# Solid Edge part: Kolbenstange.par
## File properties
Username: bmolnar
Dokumentum tartalom típus: 0
Author: bmolnar
Last saved by: bmolnar
Revision: 79
Sűrűség: 0,000 kg/m^3
Pontosság: 0,990
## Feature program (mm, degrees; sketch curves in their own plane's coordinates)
base feature "unnamed BaseFeature 1"
sketch for "unnamed Protrusion 1" plane through (42.5, 0, 0) normal (1, 0, 0) x-axis (0, 0, -1)
  circle centre (0, 0) radius 31.5
extrude "unnamed Protrusion 1" add finite 17.85 along +normal
sketch for "Kihúzás_4" #1 plane through (42.5, 0, 0) normal (1, 0, 0) x-axis (0, 0, -1)
  circle centre (0, 0) radius 8
sketch for "Kihúzás_4" #2 plane through (42.5, 0, 0) normal (1, 0, 0) x-axis (0, 0, -1)
  circle centre (0, 0) radius 31.5
extrude "Kihúzás_4" add finite 10.85 along -normal
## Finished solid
Body 1: solid body, 14 faces, 20 edges, 8 vertices.
  Faces by surface: plane 8, cylinder 4, cone 1, torus 1
  Edges by curve: circle 10, line 6, curve on surface 2, ellipse 2
Bounding box of the edges (mm; curved faces can reach further): 70.350 x 63.000 x 63.000, from (-10, -31.5, -31.5) to (60.35, 31.5, 31.5).
Cylindrical faces by radius (mm): R3.3235 x1, R4.125 x1, R8 x1, R31.5 x1
Conical faces (half-angle, radius in mm at the cone's reference point): 59 deg R1.6618 x1
Toroidal faces (ring radius, tube radius in mm): R6.2 r1.8 x1
Planar faces by outward normal: +x 1, +y 1, -x 3, -y 1, oblique 2
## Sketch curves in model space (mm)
circle centre (42.5, 0, 0) radius 31.5
circle centre (42.5, 0, 0) radius 8
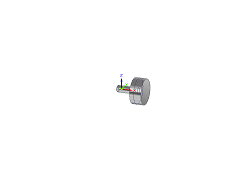
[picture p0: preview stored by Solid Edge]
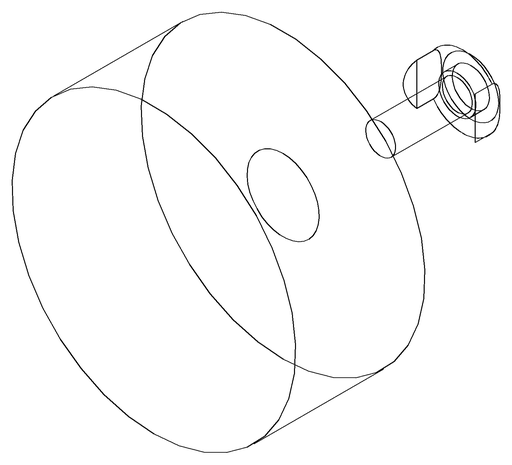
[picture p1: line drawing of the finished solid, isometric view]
